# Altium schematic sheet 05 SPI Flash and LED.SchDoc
size 299 x 210 mm
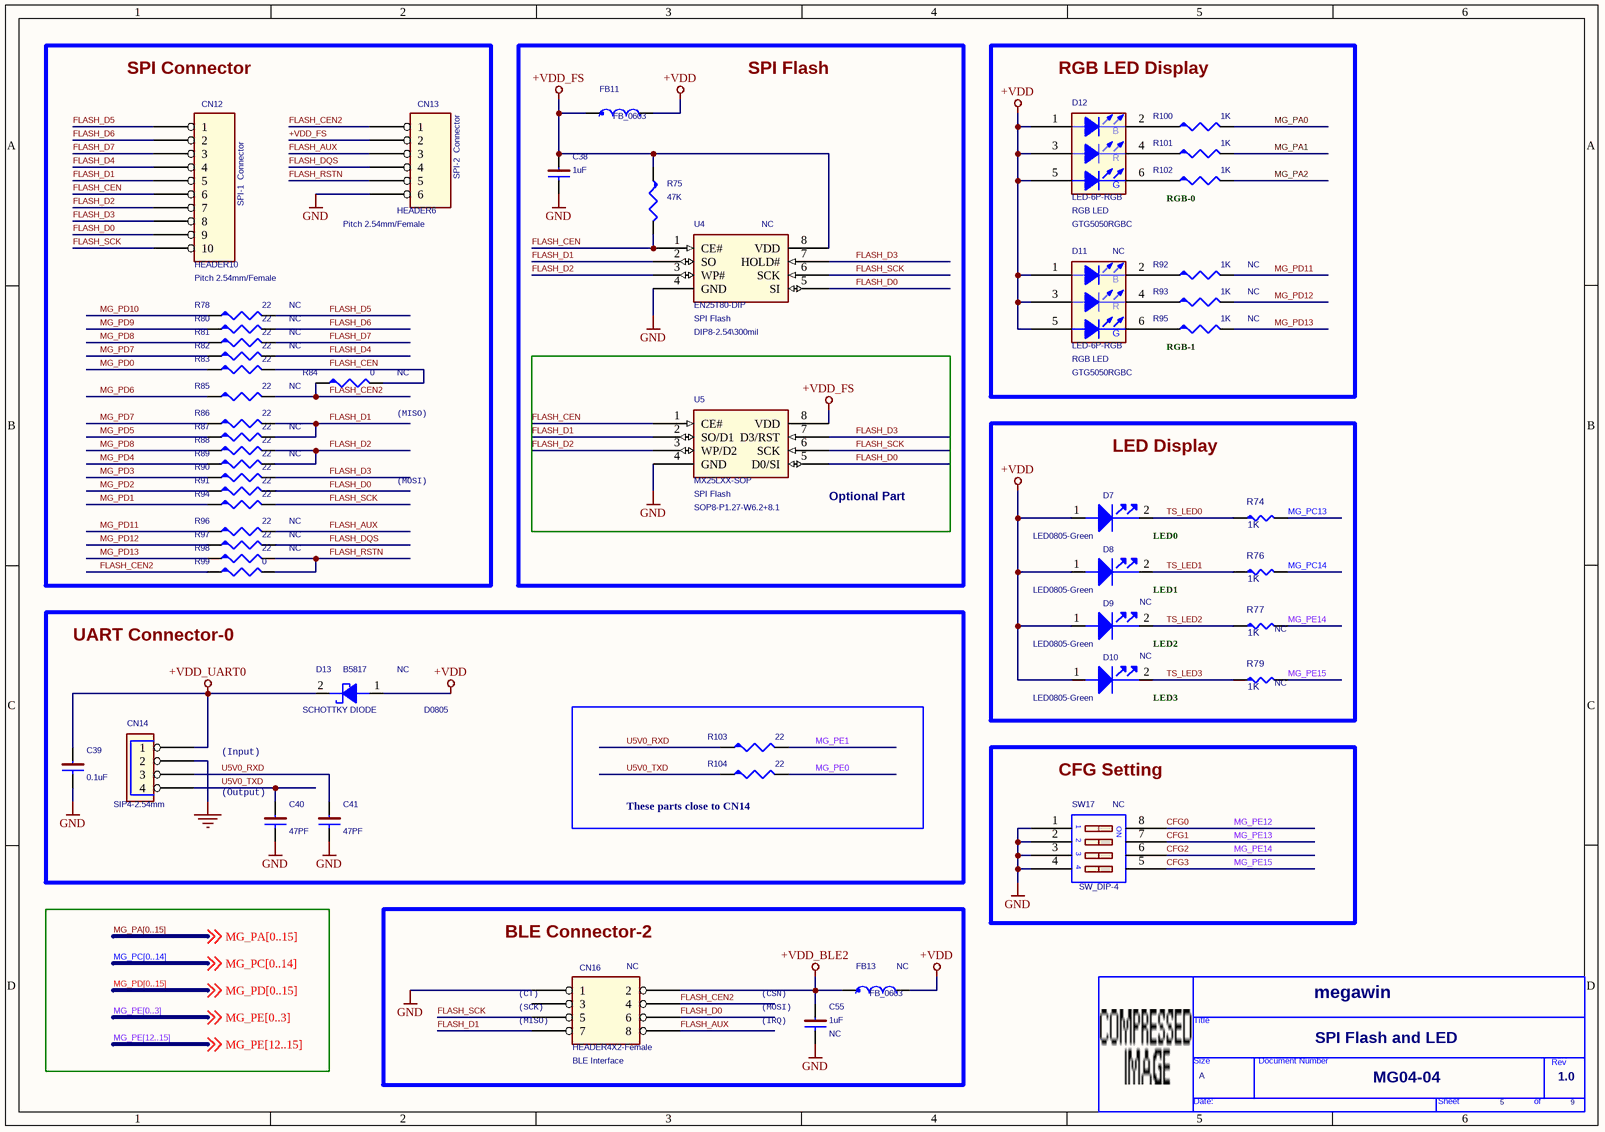
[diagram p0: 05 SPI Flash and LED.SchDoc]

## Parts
*  OrgName: megawin  Doc: MG04-04  RevCode: 1.0  Title: SPI Flash and LED  Page Size: A  Page Number: 5  Page Count: 9  (hidden comment: TitleBlock_MegaWin)  (graphical)
C38  1uF  [C-0603]
C39  0.1uF  [C-0603]
C40  47PF  [C-0603]
C41  47PF  [C-0603]
C55  1uF  Assembly: NC  [C-0603]
CN12  HEADER10  Function: SPI-1  Connector  Package: Pitch 2.54mm/Female  [SIP10-P2.54]
CN13  HEADER6  Function: SPI-2  Connector  Package: Pitch 2.54mm/Female  [SIP6-P2.54]
CN14  SIP4-2.54mm  [HD4-P2.54-Z12.4X5.7X7-UL]
CN16  HEADER4X2-Female  Function: BLE Interface  Assembly: NC  [HD4X2-P2.54]
D7  LED0805-Green  [LED-0805]
D8  LED0805-Green  [LED-0805]
D9  LED0805-Green  Assembly: NC  [LED-0805]
D10  LED0805-Green  Assembly: NC  [LED-0805]
D11  LED-6P-RGB  Function: RGB LED  Assembly: NC  Package: GTG5050RGBC  [LED-6P-RGB-50X50]
D12  LED-6P-RGB  Function: RGB LED  Package: GTG5050RGBC  [LED-6P-RGB-50X50]
D13  B5817  Package: D0805  Function: SCHOTTKY DIODE  Assembly: NC  [D-0805]
FB11  FB_0603  [L-0603]
FB13  FB_0603  Assembly: NC  [L-0603]
R74  1K  [R-0603]
R75  47K  [R-0603]
R76  1K  [R-0603]
R77  1K  Assembly: NC  [R-0603]
R78  22  Assembly: NC  [R-0603]
R79  1K  Assembly: NC  [R-0603]
R80  22  Assembly: NC  [R-0603]
R81  22  Assembly: NC  [R-0603]
R82  22  Assembly: NC  [R-0603]
R83  22  [R-0603]
R84  0  Assembly: NC  [R-0603]
R85  22  Assembly: NC  [R-0603]
R86  22  [R-0603]
R87  22  Assembly: NC  [R-0603]
R88  22  [R-0603]
R89  22  Assembly: NC  [R-0603]
R90  22  [R-0603]
R91  22  [R-0603]
R92  1K  Assembly: NC  [R-0603]
R93  1K  Assembly: NC  [R-0603]
R94  22  [R-0603]
R95  1K  Assembly: NC  [R-0603]
R96  22  Assembly: NC  [R-0603]
R97  22  Assembly: NC  [R-0603]
R98  22  Assembly: NC  [R-0603]
R99  0  [R-0603]
R100  1K  [R-0603]
R101  1K  [R-0603]
R102  1K  [R-0603]
R103  22  [R-0603]
R104  22  [R-0603]
SW17  SW_DIP-4  Assembly: NC  [SW-DIP4]
U4  EN25T80-DIP  Assembly: NC  Function: SPI Flash  Package: DIP8-2.54\300mil  [DIP8-P2.54-W7.62]
U5  MX25LXX-SOP  Function: SPI Flash  [SOP8-P1.27-W6.2+8.1]

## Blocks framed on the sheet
SPI Connector: CN12 CN13 R78 R80-R91 R94 R96-R99
SPI Flash: C38 FB11 R75 U4
RGB LED Display: D11 D12 R92 R93 R95 R100-R102
Optional Part: U5
LED Display: D7-D10 R74 R76 R77 R79
UART Connector-0: C39-C41 CN14 D13
These parts close to CN14: R103 R104
CFG Setting: SW17
BLE Connector-2: C55 CN16 FB13

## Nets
+VDD: D7.1(A) D8.1(A) D9.1(A) D10.1(A) D11.1 D11.3 D11.5 D12.1 D12.3 D12.5 D13.1(ANODE) FB11.2 FB13.2
+VDD_BLE2: C55.1 CN16.2 FB13.1
+VDD_FS: C38.1 CN13.2 FB11.1 R75.1 U4.8(VDD) U5.8(VDD)
+VDD_UART0: C39.1 CN14.1 D13.2(CATHODE)
GND: C38.2 C39.2 C40.2 C41.2 C55.2 CN13.6 CN14.2 CN16.1 SW17.1(A1) SW17.2(A2) SW17.3(A3) SW17.4(A4) U4.4(GND) U5.4(GND)
CFG0: SW17.8(B1)  [also labelled MG_PE12]
CFG1: SW17.7(B2)  [also labelled MG_PE13]
CFG2: R77.2 SW17.6(B3)  [also labelled MG_PE14]
CFG3: R79.2 SW17.5(B4)  [also labelled MG_PE15]
FLASH_AUX: CN13.3 CN16.8 R96.2
FLASH_CEN: CN12.6 R75.2 R83.2 R84.2 U4.1(CE#) U5.1(CE#)
FLASH_CEN2: CN13.1 CN16.4 R84.1 R85.2 R99.1
FLASH_D0: CN12.9 CN16.6 R91.2 U4.5(SI) U5.5(D0/SI)
FLASH_D1: CN12.5 CN16.7 R86.2 R87.2 U4.2(SO) U5.2(SO/D1)
FLASH_D2: CN12.7 R88.2 R89.2 U4.3(WP#) U5.3(WP/D2)
FLASH_D3: CN12.8 R90.2 U4.7(HOLD#) U5.7(D3/RST)
FLASH_D4: CN12.4 R82.2
FLASH_D5: CN12.1 R78.2
FLASH_D6: CN12.2 R80.2
FLASH_D7: CN12.3 R81.2
FLASH_DQS: CN13.4 R97.2
FLASH_RSTN: CN13.5 R98.2 R99.2
FLASH_SCK: CN12.10 CN16.5 R94.2 U4.6(SCK) U5.6(SCK)
MG_PA0: R100.2
MG_PA1: R101.2
MG_PA2: R102.2
MG_PC13: R74.2
MG_PC14: R76.2
MG_PD0: R83.1
MG_PD1: R94.1
MG_PD2: R91.1
MG_PD3: R90.1
MG_PD4: R89.1
MG_PD5: R87.1
MG_PD6: R85.1
MG_PD7: R82.1 R86.1
MG_PD8: R81.1 R88.1
MG_PD9: R80.1
MG_PD10: R78.1
MG_PD11: R92.2 R96.1
MG_PD12: R93.2 R97.1
MG_PD13: R95.2 R98.1
MG_PE0: R104.2
MG_PE1: R103.2
TS_LED0: D7.2(C) R74.1
TS_LED1: D8.2(C) R76.1
TS_LED2: D9.2(C) R77.1
TS_LED3: D10.2(C) R79.1
U5V0_RXD: C41.1 CN14.3 R103.1
U5V0_TXD: C40.1 CN14.4 R104.1
NetD11_2: D11.2 R92.1
NetD11_4: D11.4 R93.1
NetD11_6: D11.6 R95.1
NetD12_2: D12.2 R100.1
NetD12_4: D12.4 R101.1
NetD12_6: D12.6 R102.1

Not connected (* = marked no-connect by the designer): CN16 3

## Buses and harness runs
bus MG_PA[0..15]
bus MG_PC[0..14]
bus MG_PD[0..15]
bus MG_PE[0..3]
bus MG_PE[12..15]

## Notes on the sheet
- (near R102) RGB-0
- (near R95) RGB-1
- (near R84) (MISO)
- (MOSI)
- LED0
- LED1
- LED2
- (near D10) LED3
- (Input)
- (near C40) (Output)
- (near CN16) (CT)
- (near CN16) (SCK)
- (near C55) (MOSI)
- (near C55) (CSN)
- (near CN16) (MISO)
- (near C55) (IRQ)

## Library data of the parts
C38-C41 C55 = CAP-NP
CN14 = SIP4
CN16 = HEADER4X2
D7 D9 D10 = LED: CISPartType: Diodes\LED; ATHEROS KEY: 127-00026-000; AtherosDescription: LED, THRU_HOLE,GREEN,3.0MM RADIAL
D8 = LED: CISPartType: Diodes\LED; AtherosDescription: LED, THRU_HOLE,GREEN,3.0MM RADIAL; ATHEROS KEY: 127-00026-000
D13 = DIODE-SCHOTTKY-2
FB11 FB13 = FB2
R74 R76 R77 R79 = R2X: Asm-Lvl: _; Asm Comm: 5010; CLASS: DISCRETE; New Description: R,resistor,56ohm/5%/1/10W,0603; New PN: R11-0560013
R75 R103 R104 = R
R78 R80-R102 = R: 2ND PART FIELD: SMD_0805
SW17 = SW-DIP4
U4 = ICM-25FXX
U5 = ICM-25LXX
